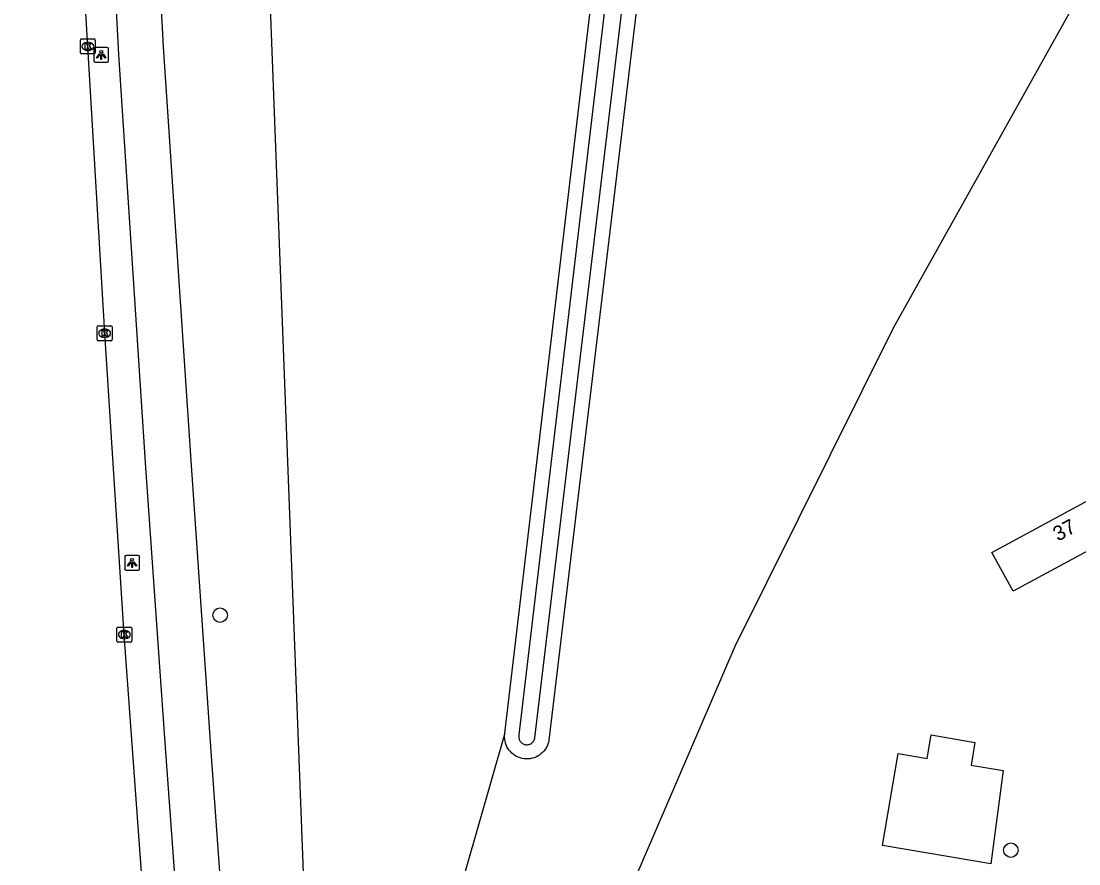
# Model space of a CAD drawing. Extents: x 159451 to 160663, y 388402 to 389723.
# Drawn here: x 159455.9 to 159527.4, y 389321.7 to 389378.7 of the extents above; entities that cross this region are included whole.
import ezdxf

# ---------------------------------------------------------------- set-up
doc = ezdxf.new("R2010")
doc.units = 0
for name, color, linetype in [('IMGEO_Boom', 7, 'Continuous'), ('IMGEO_Fietspad_gesloten', 7, 'Continuous'), ('IMGEO_Greppel_droge_sloot', 7, 'Continuous'), ('IMGEO_Kolk', 7, 'Continuous'), ('IMGEO_Lichtpunt', 7, 'Continuous'), ('IMGEO_Loofbos', 7, 'Continuous'), ('IMGEO_Pand', 7, 'Continuous'), ('IMGEO_Pand_nummerreeks', 7, 'Continuous'), ('IMGEO_Pand_vergunning_verleend', 7, 'Continuous'), ('IMGEO_Rijbaan_regionaal_gesloten', 7, 'Continuous')]:
    doc.layers.add(name, color=color, linetype=linetype)

msp = doc.modelspace()

# ---------------------------------------------------------------- linework, layer by layer
at = {"layer": 'IMGEO_Boom'}
for centre in [(159469.382, 389338.533), (159522.8, 389322.657)]:
    msp.add_circle(centre, 0.489, dxfattribs=at)
at = {"layer": 'IMGEO_Fietspad_gesloten'}
for points in [[(159469.519, 389319.015), (159468.808, 389329.001), (159467.416, 389348.979), (159465.554, 389376.915), (159464.112, 389404.118), (159462.376, 389437.214), (159460.98, 389466.613), (159459.958, 389496.642), (159459.465, 389512.981), (159459.166, 389522.863), (159459.08, 389525.773)], [(159455.942, 389525.002), (159456.038, 389522.126), (159456.372, 389512.313), (159456.916, 389496.35), (159457.955, 389465.071), (159459.294, 389436.93), (159461.071, 389403.687), (159462.508, 389376.402), (159464.342, 389348.5), (159465.649, 389329.916), (159467.063, 389310.472), (159468.609, 389291.384), (159470.151, 389272.51), (159471.683, 389255.143), (159473.293, 389238.955), (159476.115, 389210.723), (159476.688, 389204.954), (159478.244, 389191.231), (159479.81, 389178.066)]]:
    msp.add_lwpolyline(points, dxfattribs=at)
at = {"layer": 'IMGEO_Greppel_droge_sloot'}
msp.add_lwpolyline([(159500.951, 389426.848), (159489.569, 389330.453), (159489.558, 389330.36), (159489.557, 389330.312), (159489.56, 389330.267), (159489.568, 389330.215), (159489.58, 389330.167), (159489.595, 389330.123), (159489.615, 389330.078), (159489.64, 389330.034), (159489.666, 389329.996), (159489.697, 389329.959), (159489.735, 389329.921), (159489.771, 389329.89), (159489.808, 389329.864), (159489.85, 389329.84), (159489.894, 389329.82), (159489.942, 389329.803), (159489.991, 389329.79), (159490.038, 389329.782), (159490.087, 389329.778), (159490.135, 389329.779), (159490.184, 389329.784), (159490.233, 389329.794), (159490.28, 389329.807), (159490.324, 389329.825), (159490.369, 389329.847), (159490.408, 389329.871), (159490.449, 389329.901), (159490.485, 389329.934), (159490.518, 389329.97), (159490.548, 389330.007), (159490.574, 389330.049), (159490.598, 389330.093), (159490.616, 389330.137), (159490.631, 389330.185), (159490.643, 389330.239), (159499.05, 389400.457)], dxfattribs=at)
at = {"layer": 'IMGEO_Kolk'}
for p, q in [((159459.949, 389376.529), (159459.949, 389377.381)), ((159460.024, 389377.455), (159460.876, 389377.455)), ((159460.437, 389377.235), (159460.462, 389377.235)), ((159460.95, 389377.381), (159460.95, 389376.529)), ((159460.876, 389376.455), (159460.024, 389376.455)), ((159460.46, 389376.675), (159460.435, 389376.675)), ((159461.083, 389357.148), (159461.083, 389358)), ((159461.158, 389358.074), (159462.01, 389358.074)), ((159461.571, 389357.854), (159461.596, 389357.854)), ((159462.084, 389358), (159462.084, 389357.148)), ((159462.01, 389357.074), (159461.158, 389357.074)), ((159461.594, 389357.294), (159461.569, 389357.294)), ((159462.409, 389336.792), (159462.409, 389337.644)), ((159462.484, 389337.718), (159463.336, 389337.718)), ((159462.897, 389337.498), (159462.922, 389337.498)), ((159463.41, 389337.644), (159463.41, 389336.792)), ((159462.92, 389336.938), (159462.895, 389336.938)), ((159463.336, 389336.718), (159462.484, 389336.718))]:
    msp.add_line(p, q, dxfattribs=at)
for points in [[(159459.949, 389376.529), (159459.949, 389377.381)], [(159460.024, 389377.455), (159460.876, 389377.455)], [(159460.27, 389377.155), (159460.393, 389377.155), (159460.393, 389377.004), (159460.523, 389377.155), (159460.687, 389377.155), (159460.541, 389377.004), (159460.694, 389376.755), (159460.542, 389376.755), (159460.457, 389376.919), (159460.393, 389376.852), (159460.393, 389376.755), (159460.27, 389376.755), (159460.27, 389377.155)], [(159460.95, 389377.381), (159460.95, 389376.529)], [(159460.876, 389376.455), (159460.024, 389376.455)], [(159461.083, 389357.148), (159461.083, 389358)], [(159461.158, 389358.074), (159462.01, 389358.074)], [(159461.404, 389357.774), (159461.527, 389357.774), (159461.527, 389357.623), (159461.657, 389357.774), (159461.821, 389357.774), (159461.675, 389357.623), (159461.828, 389357.374), (159461.676, 389357.374), (159461.591, 389357.538), (159461.527, 389357.471), (159461.527, 389357.374), (159461.404, 389357.374), (159461.404, 389357.774)], [(159462.084, 389358), (159462.084, 389357.148)], [(159462.01, 389357.074), (159461.158, 389357.074)], [(159462.409, 389336.792), (159462.409, 389337.644)], [(159462.484, 389337.718), (159463.336, 389337.718)], [(159463.41, 389337.644), (159463.41, 389336.792)], [(159462.73, 389337.418), (159462.853, 389337.418), (159462.853, 389337.267), (159462.983, 389337.418), (159463.147, 389337.418), (159463.001, 389337.267), (159463.154, 389337.018), (159463.002, 389337.018), (159462.917, 389337.182), (159462.853, 389337.115), (159462.853, 389337.018), (159462.73, 389337.018), (159462.73, 389337.418)], [(159463.336, 389336.718), (159462.484, 389336.718)]]:
    msp.add_lwpolyline(points, dxfattribs=at)
for centre, start, end in [((159460.026, 389377.379), 91.55205, 178.44795), ((159460.026, 389377.379), 91.55205, 178.44795), ((159460.874, 389377.379), 1.55205, 88.44795), ((159460.874, 389377.379), 1.55205, 88.44795), ((159460.026, 389376.531), 181.55205, 268.44795), ((159460.026, 389376.531), 181.55205, 268.44795), ((159460.874, 389376.531), 271.55205, 358.44795), ((159460.874, 389376.531), 271.55205, 358.44795), ((159461.16, 389357.998), 91.55205, 178.44795), ((159461.16, 389357.998), 91.55205, 178.44795), ((159462.008, 389357.998), 1.55205, 88.44795), ((159462.008, 389357.998), 1.55205, 88.44795), ((159461.16, 389357.15), 181.55205, 268.44795), ((159461.16, 389357.15), 181.55205, 268.44795), ((159462.008, 389357.15), 271.55205, 358.44795), ((159462.008, 389357.15), 271.55205, 358.44795), ((159462.486, 389337.642), 91.55205, 178.44795), ((159462.486, 389337.642), 91.55205, 178.44795), ((159463.334, 389337.642), 1.55205, 88.44795), ((159463.334, 389337.642), 1.55205, 88.44795), ((159462.486, 389336.794), 181.55205, 268.44795), ((159462.486, 389336.794), 181.55205, 268.44795), ((159463.334, 389336.794), 271.55205, 358.44795), ((159463.334, 389336.794), 271.55205, 358.44795)]:
    msp.add_arc(centre, 0.0765, start, end, dxfattribs=at)
for centre, major_axis, ratio, start_param, end_param in [((159460.436, 389376.955), (-0.387, 0.002), 0.722429, 4.712389, 7.853982), ((159460.461, 389376.955), (-0.39, 0.002), 0.717154, 1.570796, 4.712389), ((159461.57, 389357.574), (-0.387, 0.002), 0.722429, 4.712389, 7.853982), ((159461.595, 389357.574), (-0.39, 0.002), 0.717154, 1.570796, 4.712389), ((159462.896, 389337.218), (-0.387, 0.002), 0.722429, 4.712389, 7.853982), ((159462.921, 389337.218), (-0.39, 0.002), 0.717154, 1.570796, 4.712389)]:
    msp.add_ellipse(centre, major_axis=major_axis, ratio=ratio, start_param=start_param, end_param=end_param, dxfattribs=at)
at = {"layer": 'IMGEO_Lichtpunt'}
for p, q in [((159460.855, 389376.785), (159460.855, 389375.978)), ((159460.855, 389376.785), (159460.855, 389375.978)), ((159461.757, 389376.88), (159460.949, 389376.88)), ((159461.757, 389376.88), (159460.949, 389376.88)), ((159461.851, 389375.978), (159461.851, 389376.785)), ((159461.851, 389375.978), (159461.851, 389376.785)), ((159460.949, 389375.884), (159461.757, 389375.884)), ((159460.949, 389375.884), (159461.757, 389375.884)), ((159463.837, 389342.559), (159463.029, 389342.559)), ((159463.837, 389342.559), (159463.029, 389342.559)), ((159462.935, 389342.464), (159462.935, 389341.657)), ((159462.935, 389342.464), (159462.935, 389341.657)), ((159463.931, 389341.657), (159463.931, 389342.464)), ((159463.931, 389341.657), (159463.931, 389342.464)), ((159463.029, 389341.563), (159463.837, 389341.563)), ((159463.029, 389341.563), (159463.837, 389341.563))]:
    msp.add_line(p, q, dxfattribs=at)
for points in [[(159461.229, 389376.449), (159461.268, 389376.421), (159461.08, 389376.159), (159461.042, 389376.186), (159461.229, 389376.449)], [(159461.331, 389376.401), (159461.378, 389376.401), (159461.378, 389376.079), (159461.331, 389376.079), (159461.331, 389376.401)], [(159461.441, 389376.421), (159461.479, 389376.448), (159461.666, 389376.186), (159461.627, 389376.158), (159461.441, 389376.421)], [(159463.309, 389342.128), (159463.348, 389342.1), (159463.16, 389341.838), (159463.122, 389341.865), (159463.309, 389342.128)], [(159463.411, 389342.08), (159463.458, 389342.08), (159463.458, 389341.758), (159463.411, 389341.758), (159463.411, 389342.08)], [(159463.521, 389342.1), (159463.559, 389342.127), (159463.746, 389341.865), (159463.707, 389341.837), (159463.521, 389342.1)]]:
    msp.add_lwpolyline(points, dxfattribs=at)
for centre in [(159461.354, 389376.583), (159463.434, 389342.262)]:
    msp.add_circle(centre, 0.0994, dxfattribs=at)
for centre, start, end in [((159460.949, 389376.785), 90, 180), ((159460.949, 389376.785), 90, 180), ((159461.757, 389376.785), 0, 90), ((159461.757, 389376.785), 0, 90), ((159460.949, 389375.978), 180, 270), ((159460.949, 389375.978), 180, 270), ((159461.757, 389375.978), 270, 0), ((159461.757, 389375.978), 270, 360), ((159463.029, 389342.464), 90, 180), ((159463.029, 389342.464), 90, 180), ((159463.837, 389342.464), 0, 90), ((159463.837, 389342.464), 0, 90), ((159463.029, 389341.657), 180, 270), ((159463.029, 389341.657), 180, 270), ((159463.837, 389341.657), 270, 0), ((159463.837, 389341.657), 270, 360)]:
    msp.add_arc(centre, 0.0946, start, end, dxfattribs=at)
at = {"layer": 'IMGEO_Loofbos'}
for points in [[(159488.618, 389330.562), (159500, 389426.958), (159502.713, 389450.674), (159503.575, 389456.3), (159504.702, 389461.528), (159506.187, 389466.881), (159508.076, 389471.717), (159511.76, 389477.052), (159516.652, 389481.479), (159520.54, 389484.356), (159524.316, 389486.573), (159529.533, 389488.524), (159536.947, 389490.758), (159549.249, 389493.781), (159576.458, 389500), (159636.811, 389510.141), (159699.069, 389520.602), (159714.899, 389522.582), (159722.507, 389523.318), (159725.623, 389523.469), (159729.75, 389522.513)], [(159467.537, 389516.526), (159475.08, 389318.792)], [(159485.81, 389295.214), (159491.991, 389308.123), (159504.183, 389336.444), (159514.866, 389357.937), (159544.814, 389411.565), (159556.465, 389431.123), (159566.644, 389445.466), (159585.18, 389466.829), (159590.702, 389478.946), (159594.278, 389488.578), (159596.128, 389493.71), (159598.507, 389500.31)], [(159500, 389400.345), (159491.588, 389330.086), (159491.585, 389330.07), (159491.557, 389329.939), (159491.516, 389329.81), (159491.465, 389329.686), (159491.402, 389329.567), (159491.33, 389329.454), (159491.247, 389329.348), (159491.155, 389329.249), (159491.055, 389329.16), (159490.947, 389329.079), (159490.833, 389329.009), (159490.712, 389328.949), (159490.587, 389328.9), (159490.458, 389328.863), (159490.326, 389328.837), (159490.192, 389328.823), (159490.058, 389328.821), (159489.924, 389328.831), (159489.791, 389328.853), (159489.661, 389328.887), (159489.534, 389328.932), (159489.412, 389328.988), (159489.295, 389329.055), (159489.185, 389329.132), (159489.083, 389329.219), (159488.988, 389329.315), (159488.902, 389329.418), (159488.826, 389329.529), (159488.76, 389329.647), (159488.705, 389329.769), (159488.661, 389329.896), (159488.629, 389330.027), (159488.608, 389330.16), (159488.599, 389330.294), (159488.603, 389330.428), (159488.618, 389330.562)], [(159488.618, 389330.562), (159485.934, 389321.215), (159479.261, 389319.665), (159475.672, 389318.831), (159475.08, 389318.792)]]:
    msp.add_lwpolyline(points, dxfattribs=at)
at = {"layer": 'IMGEO_Pand'}
msp.add_lwpolyline([(159531.423, 389344.725), (159522.948, 389340.15), (159521.508, 389342.76), (159530.004, 389347.358), (159531.423, 389344.725)], dxfattribs=at)
at = {"layer": 'IMGEO_Pand_vergunning_verleend'}
msp.add_lwpolyline([(159514.125, 389322.975), (159515.179, 389329.187), (159517.143, 389328.854), (159517.413, 389330.443), (159520.37, 389329.941), (159520.111, 389328.409), (159522.274, 389328.042), (159521.436, 389321.734), (159514.125, 389322.975)], dxfattribs=at)
at = {"layer": 'IMGEO_Rijbaan_regionaal_gesloten'}
msp.add_lwpolyline([(159475.213, 389199.409), (159473.713, 389213.767), (159472.153, 389229.121), (159470.673, 389244.477), (159469.405, 389257.836), (159468.669, 389266.005), (159467.728, 389277.179), (159466.081, 389296.525), (159464.392, 389316.843), (159462.91, 389337.218), (159462.193, 389348.076), (159461.584, 389357.574), (159460.45, 389376.955), (159459.237, 389397.341)], dxfattribs=at)

# ---------------------------------------------------------------- texts
at = {"layer": 'IMGEO_Pand_nummerreeks'}
msp.add_text('37', height=1, rotation=28.36141, dxfattribs=at).set_placement((159525.985, 389343.494))

doc.saveas('drawing.dxf')
